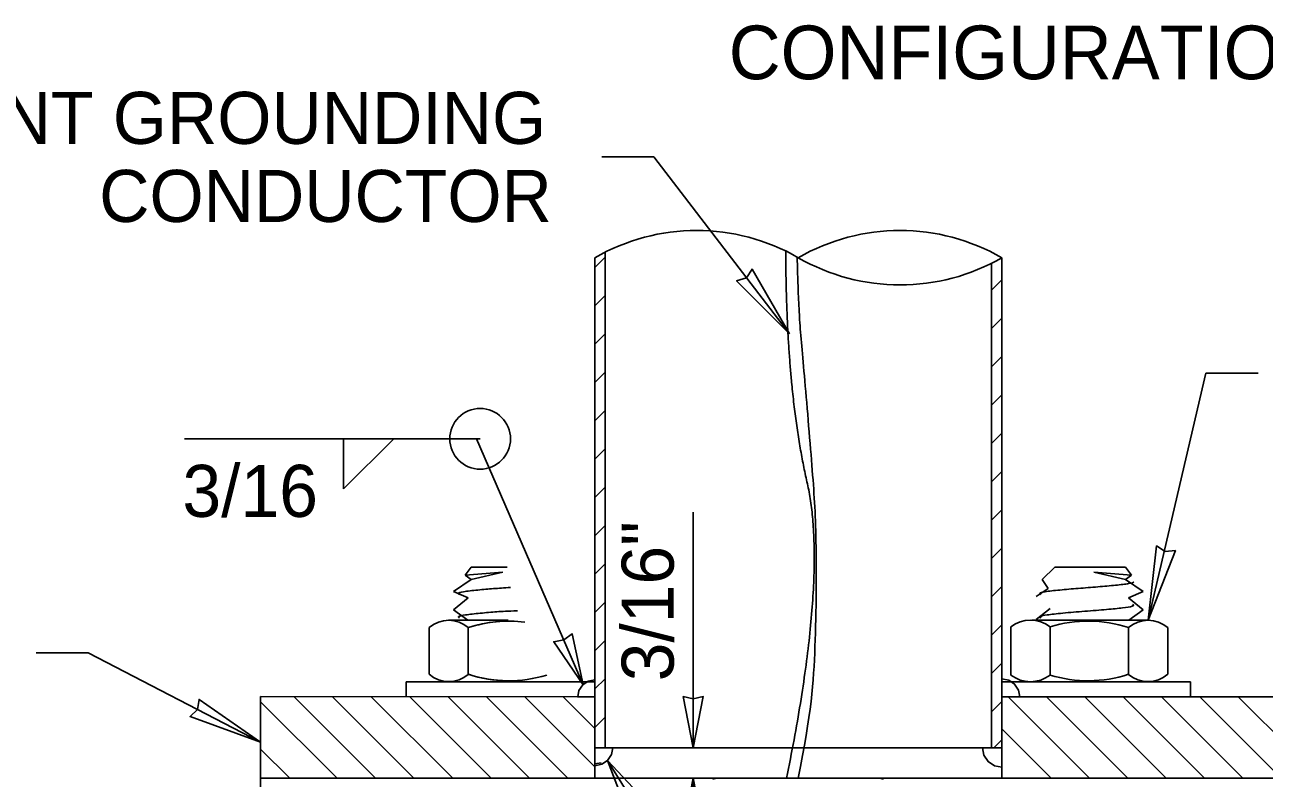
# Model space of a CAD drawing. Extents: x 99862 to 103680, y 99470 to 105076.
# Drawn here: x 102153.5 to 102534.3, y 100879.4 to 101111 of the extents above; entities that cross this region are included whole.
import ezdxf

# ---------------------------------------------------------------- set-up
doc = ezdxf.new("R2010")
doc.units = 0
for name, color, linetype in [('Level 11', 7, 'Continuous'), ('Level 12', 7, 'Continuous'), ('Level 15', 7, 'Continuous'), ('Level 16', 7, 'Continuous'), ('Level 2', 7, 'Continuous'), ('Level 20', 7, 'Continuous'), ('Level 21', 7, 'Continuous'), ('Level 25', 7, 'Continuous'), ('Level 32', 7, 'Continuous'), ('Level 4', 7, 'Continuous'), ('Level 5', 7, 'Continuous'), ('Level 9', 7, 'Continuous')]:
    doc.layers.add(name, color=color, linetype=linetype)

msp = doc.modelspace()

# ---------------------------------------------------------------- linework, layer by layer
at = {"layer": 'Level 11'}
for p, q in [((102225.94, 100904.48), (102225.94, 100879.36)), ((102328.63, 100904.36), (102225.94, 100904.48)), ((102225.94, 100902.87), (102249.45, 100879.36)), ((102236.23, 100904.36), (102261.23, 100879.36)), ((102248.02, 100904.36), (102273.02, 100879.36)), ((102259.91, 100904.44), (102284.98, 100879.36)), ((102271.77, 100904.36), (102296.77, 100879.36)), ((102283.55, 100904.36), (102308.55, 100879.36)), ((102295.34, 100904.36), (102320.34, 100879.36)), ((102307.12, 100904.36), (102328.63, 100882.86)), ((102318.91, 100904.36), (102328.63, 100894.64)), ((102328.63, 100879.36), (102328.63, 100904.36)), ((102455.58, 100904.36), (102480.58, 100879.36)), ((102467.37, 100904.36), (102492.37, 100879.36)), ((102479.15, 100904.36), (102504.15, 100879.36)), ((102490.94, 100904.36), (102515.94, 100879.36)), ((102502.72, 100904.36), (102527.72, 100879.36)), ((102514.51, 100904.36), (102539.51, 100879.36)), ((102526.29, 100904.36), (102551.29, 100879.36)), ((102453.63, 100894.53), (102468.8, 100879.36)), ((102225.94, 100888.3), (102234.88, 100879.36)), ((102225.94, 100879.36), (102328.63, 100879.36))]:
    msp.add_line(p, q, dxfattribs=at)
for points in [[(102453.63, 100879.36), (102556.32, 100879.36), (102556.32, 100904.36), (102453.63, 100904.36)], [(102453.63, 100904.36), (102453.63, 100879.36)], [(102366.13, 100879.36), (102359.88, 100879.36), (102346.94, 100879.36), (102337, 100879.36), (102330.76, 100879.36), (102328.63, 100879.36)], [(102453.63, 100879.36), (102451.5, 100879.36), (102445.26, 100879.36), (102435.33, 100879.36), (102416.13, 100879.36)]]:
    msp.add_lwpolyline(points, dxfattribs=at)
at = {"layer": 'Level 12'}
msp.add_line((102225.94, 100779.48), (102225.94, 100879.48), dxfattribs=at)
at = {"layer": 'Level 15'}
for p, q in [((102346.75, 101070.4), (102330.75, 101070.4)), ((102388.42, 101015.97), (102346.75, 101070.4)), ((102498.59, 100927.93), (102516.35, 101003.88)), ((102532.35, 101003.88), (102516.35, 101003.88)), ((102325, 100908.1), (102292.23, 100983.72)), ((102358.85, 100888.74), (102358.85, 100961.17)), ((102173, 100917.95), (102157, 100917.95)), ((102225.94, 100890.5), (102173, 100917.95)), ((102332.53, 100884.84), (102362.65, 100836.18)), ((102358.85, 100879.36), (102358.85, 100851.72))]:
    msp.add_line(p, q, dxfattribs=at)
for points in [[(102388.42, 101015.97), (102372.17, 101032.28), (102375.18, 101033.26), (102376.91, 101035.91)], [(102498.59, 100927.93), (102506.97, 100949.38), (102503.82, 100949.07), (102501.17, 100950.81)], [(102325, 100908.1), (102321.65, 100923.77), (102319.1, 100921.88), (102315.98, 100921.34)], [(102225.94, 100890.5), (102207.02, 100903.62), (102206.59, 100900.48), (102204.28, 100898.31)], [(102358.85, 100888.74), (102355.77, 100904.46), (102358.85, 100903.74), (102361.94, 100904.46)], [(102332.53, 100884.84), (102343.5, 100873.15), (102340.5, 100872.13), (102338.27, 100869.87)], [(102358.85, 100879.36), (102355.77, 100863.64), (102358.85, 100864.37), (102361.94, 100863.64)]]:
    msp.add_lwpolyline(points, close=True, dxfattribs=at)
at = {"layer": 'Level 16'}
for p, q in [((102302, 100927.93), (102283.67, 100927.93)), ((102462.85, 100927.93), (102498.59, 100927.93)), ((102277.71, 100911.31), (102277.71, 100925.68)), ((102289.7, 100925.68), (102289.7, 100911.31)), ((102456.42, 100925.91), (102456.42, 100911.09)), ((102468.47, 100925.91), (102468.47, 100911.09)), ((102492.57, 100925.68), (102492.57, 100911.31)), ((102504.61, 100911.31), (102504.61, 100925.68)), ((102270.68, 100904.36), (102270.68, 100909.05)), ((102511.58, 100904.36), (102511.58, 100909.05)), ((102364.88, 100879.12), (102366.07, 100879.36)), ((102416.13, 100879.36), (102417.32, 100879.12))]:
    msp.add_line(p, q, dxfattribs=at)
for points in [[(102328.63, 100909.05), (102317.77, 100909.05), (102307.17, 100909.05), (102295.8, 100909.05), (102285.2, 100909.05), (102276.8, 100909.05), (102271.73, 100909.05), (102270.68, 100909.05)], [(102453.63, 100909.05), (102464.49, 100909.05), (102475.09, 100909.05), (102486.46, 100909.05), (102497.06, 100909.05), (102505.46, 100909.05), (102510.53, 100909.05), (102511.58, 100909.05)], [(102366.07, 100879.36), (102370.04, 100879.36), (102374.71, 100879.36), (102380.7, 100879.36), (102387.54, 100879.36), (102394.66, 100879.36), (102401.5, 100879.36), (102407.49, 100879.36), (102412.16, 100879.36), (102416.13, 100879.36)]]:
    msp.add_lwpolyline(points, dxfattribs=at)
for centre, radius, start, end in [((102283.73, 100918.74), 9.19, 49.0578, 130.9523), ((102462.45, 100918.01), 9.93, 52.6587, 127.3413), ((102498.59, 100918.74), 9.19, 49.0477, 130.9422), ((102302.11, 100888.13), 39.54, 90.1507, 108.2986), ((102302.17, 100888.13), 39.54, 82.8257, 108.2986), ((102480.15, 100888.13), 39.54, 71.7014, 107.1831), ((102283.73, 100918.25), 9.19, 229.0477, 310.9422), ((102302.11, 100948.86), 39.54, 251.7014, 270.4089), ((102302.17, 100948.86), 39.54, 251.7014, 287.1831), ((102462.45, 100918.98), 9.93, 232.6587, 307.3413), ((102480.15, 100948.86), 39.54, 252.8169, 288.2986), ((102498.59, 100918.25), 9.19, 229.0578, 310.9523)]:
    msp.add_arc(centre, radius, start, end, dxfattribs=at)
at = {"layer": 'Level 2'}
for p, q in [((102328.63, 101036.43), (102331.6, 101039.41)), ((102450.51, 101029.43), (102453.63, 101032.56)), ((102328.63, 101024.65), (102331.76, 101027.77)), ((102450.51, 101017.65), (102453.63, 101020.77)), ((102328.63, 101012.86), (102331.76, 101015.99)), ((102450.51, 101005.86), (102453.63, 101008.99)), ((102328.63, 101001.08), (102331.76, 101004.2)), ((102450.51, 100994.08), (102453.63, 100997.2)), ((102328.63, 100989.29), (102331.76, 100992.42)), ((102450.51, 100982.29), (102453.63, 100985.42)), ((102328.63, 100977.51), (102331.76, 100980.63)), ((102450.51, 100970.51), (102453.63, 100973.63)), ((102328.63, 100965.72), (102331.76, 100968.85)), ((102450.51, 100958.72), (102453.63, 100961.85)), ((102328.63, 100953.94), (102331.76, 100957.06)), ((102450.51, 100946.94), (102453.63, 100950.06)), ((102328.63, 100942.15), (102331.76, 100945.28)), ((102450.51, 100935.15), (102453.63, 100938.28)), ((102328.63, 100930.37), (102331.76, 100933.49)), ((102450.51, 100923.37), (102453.63, 100926.49)), ((102328.63, 100918.58), (102331.76, 100921.71)), ((102450.51, 100911.58), (102453.63, 100914.71)), ((102328.63, 100906.8), (102331.76, 100909.92)), ((102450.51, 100899.8), (102453.63, 100902.92)), ((102328.63, 100895.01), (102331.76, 100898.14)), ((102451.23, 100888.74), (102453.63, 100891.14)), ((102453.63, 100888.74), (102331.76, 100888.74))]:
    msp.add_line(p, q, dxfattribs=at)
for points in [[(102331.76, 100888.74), (102328.63, 100888.74), (102328.63, 101039.41)], [(102331.76, 101041.09), (102331.76, 100888.74)], [(102453.63, 101039.41), (102453.63, 100888.74), (102450.51, 100888.74)], [(102450.51, 100888.74), (102450.51, 101037.72)]]:
    msp.add_lwpolyline(points, dxfattribs=at)
for centre, start, end in [((102359.88, 100985.28), 60, 120), ((102422.38, 100985.28), 60, 120), ((102422.38, 101093.53), 240, 300)]:
    msp.add_arc(centre, 62.5, start, end, dxfattribs=at)
at = {"layer": 'Level 21'}
for p, q in [((102453.63, 100909.93), (102453.63, 100904.36)), ((102453.63, 100904.36), (102459.19, 100904.36)), ((102334.15, 100888.74), (102328.63, 100888.74)), ((102328.63, 100888.74), (102328.63, 100883.22)), ((102332.53, 100884.84), (102333.73, 100886.63)), ((102333.63, 100888.74), (102333.63, 100888.74)), ((102333.63, 100888.74), (102333.63, 100888.74)), ((102333.73, 100886.63), (102334.15, 100888.74)), ((102453.68, 100888.69), (102447.71, 100888.69)), ((102449.38, 100888.69), (102449.38, 100888.69)), ((102449.38, 100888.69), (102449.38, 100888.69)), ((102330.54, 100884.13), (102328.63, 100883.74)), ((102328.63, 100883.74), (102328.63, 100883.74)), ((102328.63, 100883.22), (102330.74, 100883.64)), ((102330.74, 100883.64), (102332.53, 100884.84)), ((102453.68, 100884.39), (102453.68, 100884.39))]:
    msp.add_line(p, q, dxfattribs=at)
for points in [[(102326.61, 100909.24), (102324.9, 100908.1), (102323.75, 100906.38), (102323.35, 100904.36), (102328.63, 100904.36), (102328.63, 100909.64), (102326.61, 100909.24)], [(102326.61, 100909.24), (102324.9, 100908.1), (102323.75, 100906.38), (102323.35, 100904.36), (102328.63, 100904.36), (102328.63, 100909.64), (102326.61, 100909.24)], [(102328.63, 100909.05), (102328.63, 100904.36), (102323.94, 100904.36)], [(102458.77, 100906.49), (102457.56, 100908.3), (102455.76, 100909.5), (102453.63, 100909.93), (102453.63, 100904.36), (102459.19, 100904.36), (102458.77, 100906.49)], [(102459.19, 100904.36), (102458.77, 100906.49), (102457.56, 100908.3), (102455.76, 100909.5), (102453.63, 100909.93)], [(102458.32, 100904.36), (102453.63, 100904.36), (102453.63, 100909.05)], [(102328.63, 100888.74), (102328.63, 100888.74), (102333.63, 100888.74), (102333.63, 100888.74)], [(102333.73, 100886.63), (102334.15, 100888.74), (102328.63, 100888.74), (102328.63, 100883.22), (102330.74, 100883.64), (102332.53, 100884.84), (102333.73, 100886.63)], [(102334.15, 100888.74), (102334.15, 100888.74), (102333.73, 100886.63), (102332.53, 100884.84), (102330.74, 100883.64)], [(102453.68, 100882.72), (102451.4, 100883.18), (102449.46, 100884.47), (102448.17, 100886.41), (102447.71, 100888.69), (102447.71, 100888.69)], [(102448.17, 100886.41), (102449.46, 100884.47), (102451.4, 100883.18), (102453.68, 100882.72), (102453.68, 100888.69), (102447.71, 100888.69), (102448.17, 100886.41)], [(102447.71, 100888.69), (102448.17, 100886.41), (102449.46, 100884.47), (102451.4, 100883.18)], [(102449.38, 100888.69), (102449.38, 100888.69), (102453.68, 100888.69), (102453.68, 100888.69)], [(102451.4, 100883.18), (102453.68, 100882.72), (102453.68, 100888.69)]]:
    msp.add_lwpolyline(points, dxfattribs=at)
at = {"layer": 'Level 25'}
for points in [[(102465.69, 100935.89), (102465.55, 100935.95), (102465, 100936.24), (102466.4, 100936.69), (102471.35, 100937.25), (102477.05, 100937.73), (102483.21, 100938.21), (102488.78, 100938.69), (102493.03, 100939.2), (102494.16, 100939.55), (102494.16, 100939.74)], [(102287.02, 100935.89), (102286.87, 100935.95), (102286.32, 100936.24), (102287.72, 100936.69), (102292.67, 100937.25), (102297.53, 100937.66), (102300.67, 100937.91), (102302.72, 100938)], [(102465.69, 100928.69), (102465.33, 100928.82), (102465.16, 100929.12), (102467.1, 100929.57), (102472.06, 100930.13), (102479.14, 100930.69), (102486.14, 100931.25), (102491.03, 100931.73), (102494.16, 100932.24), (102494.32, 100932.59), (102493.82, 100932.79)], [(102287.02, 100928.69), (102286.65, 100928.82), (102286.48, 100929.12), (102288.43, 100929.57), (102293.38, 100930.13), (102298.6, 100930.54), (102301.78, 100930.8), (102304.83, 100930.81)]]:
    msp.add_open_spline(points, degree=3, dxfattribs=at)
at = {"layer": 'Level 32'}
for points, degree in [([(102387.5, 100879.36), (102400.32, 100942.02), (102387.39, 100998.34), (102387.26, 101041.47)], 2), ([(102391.1, 100879.36), (102395.11, 100899.27), (102396.57, 100918.51), (102396.8, 100955.41), (102395.54, 100973.05), (102392.78, 101006.02), (102391.29, 101021.35), (102390.85, 101036.72), (102390.82, 101038.17), (102390.8, 101039.6)], 3)]:
    msp.add_open_spline(points, degree=degree, dxfattribs=at)
at = {"layer": 'Level 4'}
for p, q in [((102288.79, 100941.81), (102290.6, 100944.3)), ((102290.6, 100944.3), (102301.66, 100944.3)), ((102469.89, 100944.3), (102466.04, 100940.45)), ((102491.66, 100944.3), (102469.89, 100944.3)), ((102493.47, 100941.81), (102491.66, 100944.3)), ((102285.16, 100936.82), (102290.6, 100940.45)), ((102300.35, 100942.72), (102288.79, 100941.81)), ((102288.79, 100941.81), (102290.6, 100940.45)), ((102290.6, 100940.45), (102300.35, 100942.72)), ((102466.04, 100940.45), (102467.85, 100937.73)), ((102491.66, 100940.45), (102481.91, 100942.72)), ((102481.91, 100942.72), (102493.47, 100941.81)), ((102493.47, 100941.81), (102491.66, 100940.45)), ((102497.1, 100936.82), (102491.66, 100940.45)), ((102289.7, 100934.78), (102285.16, 100936.82)), ((102467.85, 100937.73), (102464.22, 100935.23)), ((102492.57, 100934.78), (102497.1, 100936.82)), ((102285.16, 100931.15), (102289.7, 100934.78)), ((102497.1, 100931.15), (102492.57, 100934.78)), ((102289.58, 100927.93), (102285.16, 100931.15)), ((102468.53, 100931.6), (102464.22, 100928.2)), ((102464.22, 100928.2), (102464.49, 100927.93)), ((102492.68, 100927.93), (102497.1, 100931.15))]:
    msp.add_line(p, q, dxfattribs=at)
at = {"layer": 'Level 5'}
msp.add_lwpolyline([(102516.13, 100904.36), (102516.13, 100904.36), (102508.63, 100904.36)], dxfattribs=at)
at = {"layer": 'Level 9'}
for p, q in [((102293.38, 100983.72), (102202.52, 100983.72)), ((102251.45, 100983.72), (102251.45, 100968.31)), ((102266.86, 100983.72), (102251.45, 100968.31))]:
    msp.add_line(p, q, dxfattribs=at)
msp.add_circle((102293.38, 100983.72), 9.33, dxfattribs=at)

# ---------------------------------------------------------------- texts
at = {"layer": 'Level 20'}
for s, height, p in [('CONFIGURATIONS VARY AMONG DIFFERENT MANUFACTURERS', 16.5, (102369.76, 101094.28)), ('EQUIPMENT GROUNDING', 16, (102047.4, 101074.4)), ('CONDUCTOR', 16, (102176.35, 101050.4)), ('3/16', 16, (102201.92, 100959.72))]:
    msp.add_text(s, height=height, dxfattribs=at).set_placement(p)
msp.add_text('3/16"', height=16, rotation=90, dxfattribs=at).set_placement((102352.85, 100909.17))

doc.saveas('drawing.dxf')
